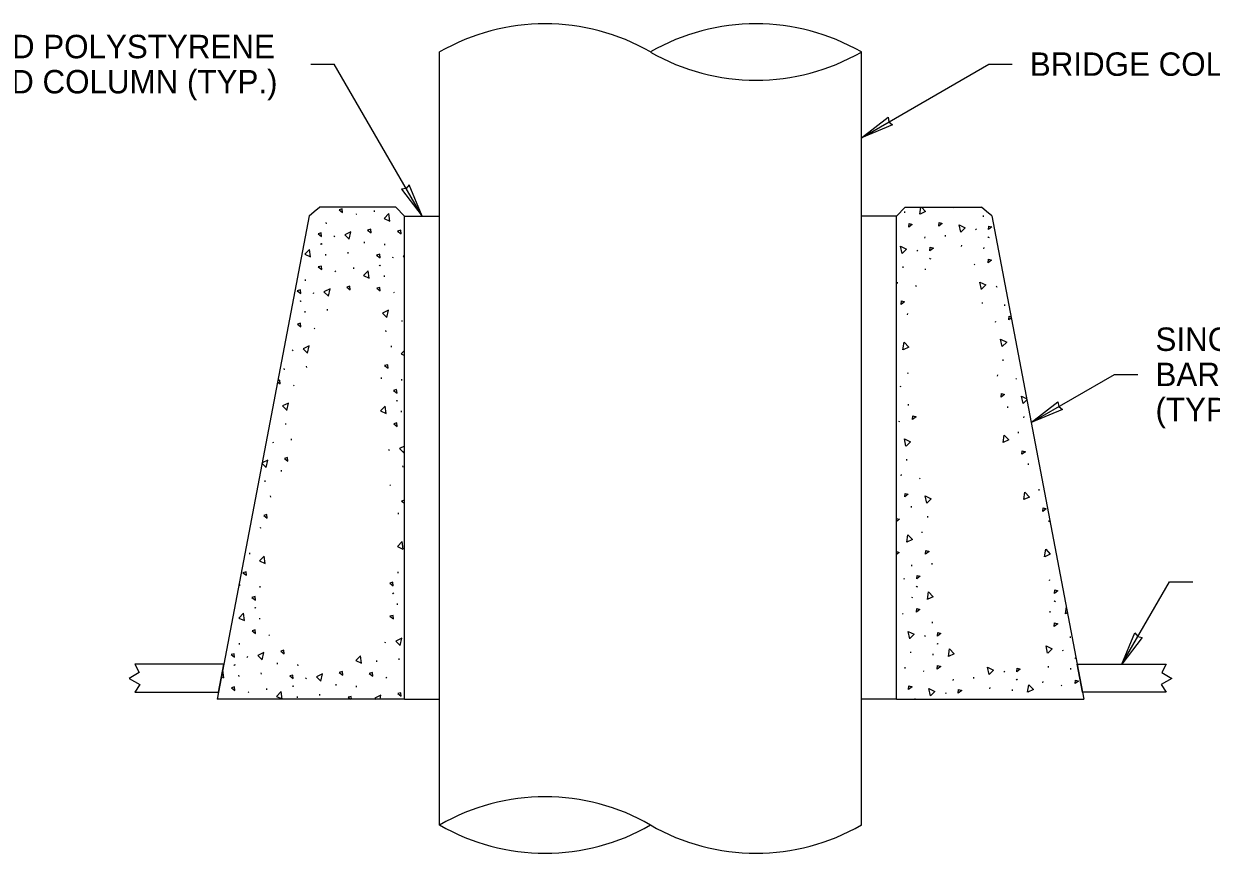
# Model space of a CAD drawing. Extents: x 99862 to 103151, y 100000 to 102076.
# Drawn here: x 100993 to 101804, y 100865 to 101431 of the extents above; entities that cross this region are included whole.
import ezdxf

# ---------------------------------------------------------------- set-up
doc = ezdxf.new("R2010")
doc.units = 0
for name, color, linetype in [('Level 13', 7, 'Continuous'), ('Level 15', 7, 'Continuous'), ('Level 2', 7, 'Continuous'), ('Level 20', 7, 'Continuous'), ('Level 45', 7, 'Continuous'), ('Level 49', 7, 'Continuous')]:
    doc.layers.add(name, color=color, linetype=linetype)

msp = doc.modelspace()

# ---------------------------------------------------------------- linework, layer by layer
at = {"layer": 'Level 13'}
for p, q in [((101220.06, 101301.42), (101219.54, 101301.04)), ((101232.44, 101302.97), (101232.38, 101303.84)), ((101594.39, 101302.2), (101594.45, 101303.07)), ((101627.68, 101306.07), (101628.17, 101305.71)), ((101648.21, 101299.49), (101648.27, 101300.36)), ((101199.51, 101294.82), (101199.45, 101295.69)), ((101642.77, 101291.26), (101643.12, 101290.54)), ((101204.95, 101286.59), (101204.6, 101285.87)), ((101225.56, 101281.47), (101225.5, 101282.34)), ((101608.23, 101284.94), (101608.29, 101285.81)), ((101622.16, 101286.13), (101622.22, 101287.01)), ((101651.22, 101285.75), (101651.74, 101285.37)), ((101651.62, 101285.68), (101652.14, 101285.3)), ((101196.09, 101281.01), (101195.58, 101280.63)), ((101196.5, 101281.08), (101195.98, 101280.7)), ((101214.44, 101274.55), (101214.38, 101275.42)), ((101239.48, 101280.27), (101239.42, 101281.14)), ((101602.79, 101276.71), (101603.15, 101275.99)), ((101633.28, 101279.22), (101633.34, 101280.09)), ((101648.55, 101277.77), (101648.61, 101278.64)), ((101199.17, 101273.1), (101199.11, 101273.98)), ((101236.07, 101266.46), (101235.55, 101266.08)), ((101236.47, 101266.53), (101235.95, 101266.15)), ((101244.93, 101272.04), (101244.57, 101271.32)), ((101611.25, 101271.2), (101611.77, 101270.82)), ((101611.65, 101271.13), (101612.17, 101270.75)), ((101641.85, 101267.11), (101642.36, 101266.73)), ((101205.87, 101262.44), (101205.36, 101262.06)), ((101218.25, 101263.99), (101218.19, 101264.86)), ((101239.14, 101258.55), (101239.08, 101259.43)), ((101593.31, 101264.67), (101593.37, 101265.54)), ((101608.58, 101263.22), (101608.64, 101264.09)), ((101185.32, 101255.84), (101185.26, 101256.71)), ((101589.5, 101254.1), (101589.56, 101254.98)), ((101601.87, 101252.56), (101602.39, 101252.18)), ((101656.95, 101252.28), (101657.31, 101251.56)), ((101181.91, 101242.03), (101181.39, 101241.65)), ((101182.31, 101242.1), (101181.79, 101241.72)), ((101190.77, 101247.61), (101190.41, 101246.89)), ((101245.85, 101247.89), (101245.33, 101247.51)), ((101184.98, 101234.12), (101184.92, 101235)), ((101200.25, 101235.57), (101200.19, 101236.44)), ((101647.47, 101240.24), (101647.53, 101241.11)), ((101662.74, 101238.79), (101662.8, 101239.66)), ((101251.34, 101227.94), (101251.28, 101228.81)), ((101596.38, 101232.6), (101596.44, 101233.48)), ((101656.03, 101228.13), (101656.55, 101227.75)), ((101191.69, 101223.46), (101191.17, 101223.08)), ((101240.22, 101221.02), (101240.16, 101221.89)), ((101244.03, 101210.46), (101243.97, 101211.33)), ((101176.58, 101208.63), (101176.22, 101207.91)), ((101661.65, 101201.26), (101661.72, 101202.13)), ((101170.79, 101195.14), (101170.73, 101196.02)), ((101186.06, 101196.59), (101186, 101197.46)), ((101596.64, 101192.43), (101596.7, 101193.3)), ((101237.15, 101188.96), (101237.09, 101189.83)), ((101251.08, 101187.76), (101251.02, 101188.64)), ((101657.85, 101190.69), (101657.91, 101191.56)), ((101670.22, 101189.15), (101670.74, 101188.77)), ((101177.5, 101184.48), (101176.98, 101184.1)), ((101591.2, 101184.2), (101591.55, 101183.48)), ((101247.66, 101173.96), (101247.15, 101173.58)), ((101248.07, 101174.02), (101247.55, 101173.64)), ((101596.98, 101170.71), (101597.04, 101171.58)), ((101664.73, 101169.19), (101664.79, 101170.07)), ((101250.74, 101166.05), (101250.68, 101166.92)), ((101675.84, 101162.28), (101675.9, 101163.15)), ((101171.88, 101157.61), (101171.82, 101158.48)), ((101590.28, 101160.05), (101590.79, 101159.67)), ((101672.03, 101151.71), (101672.09, 101152.59)), ((101163.31, 101145.5), (101162.79, 101145.12)), ((101175.69, 101147.05), (101175.63, 101147.92)), ((101242.33, 101140.55), (101241.98, 101139.83)), ((101251.82, 101128.51), (101251.76, 101129.39)), ((101595.9, 101133.18), (101595.96, 101134.05)), ((101678.91, 101130.21), (101678.97, 101131.09)), ((101168.81, 101125.55), (101168.74, 101126.42)), ((101592.09, 101122.62), (101592.15, 101123.49)), ((101604.46, 101121.07), (101604.98, 101120.69)), ((101157.69, 101118.63), (101157.63, 101119.5)), ((101243.26, 101116.4), (101242.74, 101116.03)), ((101686.22, 101112.73), (101686.28, 101113.61)), ((101161.5, 101108.07), (101161.44, 101108.94)), ((101248.75, 101096.45), (101248.69, 101097.32)), ((101598.97, 101101.12), (101599.03, 101101.99)), ((101610.09, 101094.2), (101610.15, 101095.07)), ((101693.1, 101091.23), (101693.16, 101092.11)), ((101154.62, 101086.57), (101154.56, 101087.44)), ((101588.81, 101085.86), (101588.97, 101085.73)), ((101606.28, 101083.64), (101606.34, 101084.51)), ((101147.31, 101069.09), (101147.25, 101069.96)), ((101248.49, 101056.27), (101248.43, 101057.15)), ((101599.23, 101060.94), (101599.29, 101061.81)), ((101613.16, 101062.14), (101613.22, 101063.01)), ((101140.43, 101047.59), (101140.37, 101048.46)), ((101154.36, 101046.39), (101154.3, 101047.26)), ((101593.79, 101052.71), (101594.14, 101051.99)), ((101602.24, 101047.2), (101602.76, 101046.82)), ((101602.65, 101047.13), (101603.16, 101046.75)), ((101693.36, 101051.06), (101693.42, 101051.93)), ((101245.07, 101042.47), (101244.56, 101042.09)), ((101245.48, 101042.54), (101244.96, 101042.16)), ((101599.57, 101039.22), (101599.63, 101040.1)), ((101150.94, 101032.58), (101150.43, 101032.21)), ((101151.34, 101032.65), (101150.83, 101032.27)), ((101248.15, 101034.56), (101248.09, 101035.43)), ((101696.37, 101037.32), (101696.89, 101036.94)), ((101696.78, 101037.25), (101697.29, 101036.87)), ((101154.02, 101024.68), (101153.96, 101025.55)), ((101592.87, 101028.56), (101593.38, 101028.18)), ((101613.41, 101021.96), (101613.48, 101022.83)), ((101693.7, 101029.34), (101693.76, 101030.21)), ((101140.17, 101007.41), (101140.11, 101008.29)), ((101160.72, 101014.01), (101160.2, 101013.63)), ((101239.74, 101009.07), (101239.39, 101008.35)), ((101607.97, 101013.73), (101608.33, 101013.01)), ((101616.43, 101008.22), (101616.95, 101007.84)), ((101616.83, 101008.15), (101617.35, 101007.77)), ((101707.55, 101012.08), (101707.61, 101012.95)), ((101145.61, 100999.18), (101145.26, 100998.46)), ((101598.49, 101001.69), (101598.55, 101002.56)), ((101613.76, 101000.24), (101613.82, 101001.12)), ((101702.11, 101003.85), (101702.46, 101003.13)), ((101136.75, 100993.6), (101136.24, 100993.23)), ((101137.16, 100993.67), (101136.64, 100993.29)), ((101166.22, 100994.06), (101166.15, 100994.93)), ((101180.14, 100992.86), (101180.08, 100993.74)), ((101233.96, 100995.58), (101233.9, 100996.45)), ((101249.23, 100997.03), (101249.17, 100997.9)), ((101594.68, 100991.13), (101594.74, 100992)), ((101692.62, 100991.81), (101692.68, 100992.68)), ((101707.89, 100990.36), (101707.95, 100991.23)), ((101710.56, 100998.34), (101711.08, 100997.96)), ((101710.96, 100998.27), (101711.48, 100997.89)), ((101139.83, 100985.7), (101139.77, 100986.57)), ((101155.1, 100987.14), (101155.04, 100988.02)), ((101185.58, 100984.64), (101185.23, 100983.91)), ((101240.66, 100984.92), (101240.15, 100984.54)), ((101607.05, 100989.58), (101607.57, 100989.2)), ((101627.6, 100982.98), (101627.66, 100983.85)), ((101641.53, 100984.18), (101641.59, 100985.05)), ((101662.13, 100989.3), (101662.49, 100988.58)), ((101670.59, 100983.79), (101671.11, 100983.41)), ((101670.99, 100983.72), (101671.51, 100983.34)), ((101146.53, 100975.03), (101146.02, 100974.65)), ((101158.91, 100976.58), (101158.85, 100977.45)), ((101176.73, 100979.06), (101176.21, 100978.68)), ((101177.13, 100979.12), (101176.61, 100978.75)), ((101206.19, 100979.51), (101206.13, 100980.38)), ((101220.12, 100978.32), (101220.06, 100979.19)), ((101622.16, 100974.75), (101622.52, 100974.03)), ((101652.65, 100977.26), (101652.71, 100978.13)), ((101667.92, 100975.81), (101667.98, 100976.69)), ((101688.81, 100981.24), (101688.87, 100982.12)), ((101701.19, 100979.7), (101701.7, 100979.32)), ((101179.8, 100971.15), (101179.74, 100972.02)), ((101195.07, 100972.59), (101195.01, 100973.47)), ((101225.56, 100970.09), (101225.55, 100970.07)), ((101601.59, 100970.07), (101601.62, 100970.5))]:
    msp.add_line(p, q, dxfattribs=at)
for points in [[(101210.51, 101302.44), (101210.27, 101304.89), (101208.14, 101304.25), (101210.51, 101302.44)], [(101242.88, 101296.61), (101242.18, 101301.69), (101239, 101298.4), (101242.8, 101296.64)], [(101604.84, 101301.28), (101605.5, 101306.07)], [(101605.82, 101306.07), (101608.72, 101303.07), (101604.92, 101301.31)], [(101230.02, 101288.59), (101229.78, 101291.04), (101227.65, 101290.39), (101230.02, 101288.59)], [(101597.24, 101292.56), (101597.48, 101295.01), (101599.6, 101294.36), (101597.24, 101292.56)], [(101617.7, 101293.25), (101617.94, 101295.7), (101620.07, 101295.06), (101617.7, 101293.25)], [(101632.63, 101288.96), (101631.55, 101293.97), (101635.67, 101291.98), (101632.7, 101289.02)], [(101651.56, 101290.79), (101651.8, 101293.24), (101653.93, 101292.59), (101651.56, 101290.79)], [(101196.16, 101286.12), (101195.91, 101288.57), (101193.79, 101287.93), (101196.16, 101286.12)], [(101215.09, 101284.3), (101216.16, 101289.31), (101212.05, 101287.31), (101215.02, 101284.36)], [(101250.48, 101287.89), (101250.24, 101290.34), (101248.12, 101289.7), (101250.48, 101287.89)], [(101188.72, 101272.18), (101188.02, 101277.26), (101184.84, 101273.97), (101188.64, 101272.21)], [(101592.66, 101274.42), (101591.58, 101279.43), (101595.69, 101277.43), (101592.73, 101274.47)], [(101611.59, 101276.24), (101611.83, 101278.69), (101613.96, 101278.04), (101611.59, 101276.24)], [(101236.13, 101271.57), (101235.89, 101274.02), (101233.76, 101273.38), (101236.13, 101271.57)], [(101252.81, 101273.14), (101252.02, 101272.76), (101252.81, 101271.98)], [(101651.4, 101268.13), (101651.64, 101270.58), (101653.76, 101269.93), (101651.4, 101268.13)], [(101196.32, 101263.46), (101196.08, 101265.91), (101193.96, 101265.27), (101196.32, 101263.46)], [(101228.69, 101257.63), (101227.99, 101262.71), (101224.81, 101259.42), (101228.61, 101257.66)], [(101200.9, 101245.32), (101201.98, 101250.33), (101197.86, 101248.33), (101200.83, 101245.38)], [(101215.83, 101249.61), (101215.59, 101252.06), (101213.46, 101251.41), (101215.83, 101249.61)], [(101236.29, 101248.91), (101236.05, 101251.36), (101233.93, 101250.72), (101236.29, 101248.91)], [(101646.82, 101249.98), (101645.74, 101254.99), (101649.85, 101253), (101646.88, 101250.04)], [(101181.97, 101247.14), (101181.73, 101249.59), (101179.6, 101248.95), (101181.97, 101247.14)], [(101591.92, 101239.72), (101592.16, 101242.17), (101594.28, 101241.53), (101591.92, 101239.72)], [(101240.87, 101230.77), (101241.95, 101235.78), (101237.84, 101233.78), (101240.81, 101230.83)], [(101182.13, 101224.48), (101181.89, 101226.93), (101179.77, 101226.29), (101182.13, 101224.48)], [(101665.58, 101229.15), (101665.83, 101231.6), (101667.06, 101231.22)], [(101667.22, 101230.4), (101665.58, 101229.15)], [(101186.71, 101206.34), (101187.79, 101211.35), (101183.68, 101209.35), (101186.65, 101206.4)], [(101593.24, 101208.77), (101593.94, 101213.85), (101597.12, 101210.56), (101593.32, 101208.8)], [(101661, 101211), (101659.93, 101216.01), (101664.04, 101214.02), (101661.07, 101211.06)], [(101252.81, 101208.18), (101250.59, 101205.9), (101252.81, 101204.87)], [(101241.62, 101196.08), (101241.37, 101198.53), (101239.25, 101197.88), (101241.62, 101196.08)], [(101166.11, 101186.9), (101167.95, 101185.5)], [(101167.95, 101185.5), (101167.7, 101187.95), (101166.23, 101187.5)], [(101247.73, 101179.06), (101247.48, 101181.51), (101245.36, 101180.87), (101247.73, 101179.06)], [(101660.26, 101176.31), (101660.51, 101178.76), (101662.63, 101178.12), (101660.26, 101176.31)], [(101675.19, 101172.02), (101674.12, 101177.04), (101677.72, 101175.29)], [(101172.53, 101167.36), (101173.6, 101172.37), (101169.49, 101170.37), (101172.46, 101167.42)], [(101240.29, 101165.12), (101239.59, 101170.2), (101236.41, 101166.92), (101240.21, 101165.15)], [(101677.84, 101174.65), (101675.26, 101172.08)], [(101599.83, 101161.07), (101600.07, 101163.52), (101602.19, 101162.88), (101599.83, 101161.07)], [(101247.89, 101156.4), (101247.65, 101158.85), (101245.52, 101158.21), (101247.89, 101156.4)], [(101595.25, 101142.93), (101594.17, 101147.94), (101598.28, 101145.94), (101595.32, 101142.98)], [(101661.59, 101145.36), (101662.29, 101150.44), (101665.47, 101147.15), (101661.67, 101145.39)], [(101252.81, 101142.91), (101249.43, 101141.27), (101252.4, 101138.32)], [(101252.47, 101138.26), (101252.81, 101139.83)], [(101674.45, 101137.33), (101674.69, 101139.78), (101676.82, 101139.14), (101674.45, 101137.33)], [(101155.5, 101131.19), (101158.27, 101128.44)], [(101158.34, 101128.38), (101159.41, 101133.39), (101155.56, 101131.52)], [(101173.27, 101132.67), (101173.03, 101135.12), (101170.9, 101134.47), (101173.27, 101132.67)], [(101252.81, 101105.97), (101250.85, 101105.37), (101252.81, 101103.88)], [(101594.51, 101108.23), (101594.75, 101110.69), (101596.87, 101110.04), (101594.51, 101108.23)], [(101609.43, 101103.95), (101608.36, 101108.96), (101612.47, 101106.96), (101609.5, 101104)], [(101675.78, 101106.38), (101676.48, 101111.46), (101679.66, 101108.17), (101675.86, 101106.41)], [(101159.08, 101093.69), (101158.84, 101096.14), (101156.71, 101095.49), (101159.08, 101093.69)], [(101688.64, 101098.35), (101688.88, 101100.8), (101691, 101100.16), (101688.64, 101098.35)], [(101588.81, 101093.62), (101590.76, 101093.03), (101588.81, 101091.53)], [(101595.83, 101077.28), (101596.54, 101082.36), (101599.72, 101079.07), (101595.91, 101077.31)], [(101251.89, 101072.62), (101251.18, 101077.69), (101248, 101074.41), (101251.8, 101072.65)], [(101608.69, 101069.25), (101608.94, 101071.71), (101611.06, 101071.06), (101608.69, 101069.25)], [(101689.96, 101067.4), (101690.67, 101072.48), (101693.85, 101069.19), (101690.05, 101067.43)], [(101157.76, 101062.73), (101157.05, 101067.81), (101153.87, 101064.53), (101157.67, 101062.76)], [(101588.81, 101070.91), (101590.6, 101070.37), (101588.81, 101069)], [(101144.89, 101054.71), (101144.65, 101057.16), (101142.53, 101056.51), (101144.89, 101054.71)], [(101245.14, 101047.57), (101244.89, 101050.02), (101242.77, 101049.38), (101245.14, 101047.57)], [(101602.58, 101052.24), (101602.83, 101054.69), (101604.95, 101054.05), (101602.58, 101052.24)], [(101151, 101037.69), (101150.76, 101040.14), (101148.64, 101039.5), (101151, 101037.69)], [(101610.02, 101038.3), (101610.72, 101043.38), (101613.9, 101040.09), (101610.1, 101038.33)], [(101696.72, 101042.36), (101696.96, 101044.81), (101699.08, 101044.16), (101696.72, 101042.36)], [(101602.42, 101029.58), (101602.66, 101032.03), (101604.78, 101031.39), (101602.42, 101029.58)], [(101704.15, 101028.42), (101704.8, 101033.1)], [(101143.57, 101023.75), (101142.86, 101028.83), (101139.68, 101025.55), (101143.48, 101023.78)], [(101245.3, 101024.92), (101245.06, 101027.37), (101242.93, 101026.72), (101245.3, 101024.92)], [(101705.57, 101029.07), (101704.23, 101028.45)], [(101151.17, 101015.03), (101150.93, 101017.48), (101148.8, 101016.84), (101151.17, 101015.03)], [(101597.84, 101011.44), (101596.76, 101016.45), (101600.87, 101014.45), (101597.91, 101011.5)], [(101616.77, 101013.26), (101617.01, 101015.71), (101619.14, 101015.07), (101616.77, 101013.26)], [(101696.55, 101019.7), (101696.79, 101022.15), (101698.92, 101021.51), (101696.55, 101019.7)], [(101249.88, 101006.77), (101250.96, 101011.78), (101246.84, 101009.78), (101249.81, 101006.83)], [(101691.97, 101001.56), (101690.9, 101006.57), (101695.01, 101004.57), (101692.04, 101001.61)], [(101136.82, 100998.71), (101136.57, 101001.16), (101134.45, 101000.52), (101136.82, 100998.71)], [(101155.75, 100996.89), (101156.82, 101001.9), (101152.71, 100999.9), (101155.68, 100996.95)], [(101170.68, 101001.18), (101170.44, 101003.63), (101168.31, 101002.98), (101170.68, 101001.18)], [(101223.51, 100994.66), (101222.81, 100999.73), (101219.63, 100996.45), (101223.43, 100994.69)], [(101624.21, 100999.32), (101624.91, 101004.4), (101628.09, 101001.11), (101624.29, 100999.35)], [(101616.61, 100990.6), (101616.85, 100993.05), (101618.97, 100992.41), (101616.61, 100990.6)], [(101652, 100987.01), (101650.92, 100992.02), (101655.03, 100990.02), (101652.07, 100987.06)], [(101670.93, 100988.83), (101671.17, 100991.28), (101673.3, 100990.64), (101670.93, 100988.83)], [(101127.75, 100985.52), (101129.3, 100984.8)], [(101129.38, 100984.77), (101128.68, 100989.85), (101128.55, 100989.72)], [(101176.79, 100984.16), (101176.55, 100986.61), (101174.42, 100985.97), (101176.79, 100984.16)], [(101195.72, 100982.34), (101196.8, 100987.35), (101192.68, 100985.35), (101195.65, 100982.4)], [(101210.65, 100986.63), (101210.41, 100989.08), (101208.28, 100988.44), (101210.65, 100986.63)], [(101231.11, 100985.94), (101230.87, 100988.39), (101228.75, 100987.74), (101231.11, 100985.94)], [(101710.74, 100980.72), (101710.98, 100983.17), (101713.1, 100982.53), (101710.74, 100980.72)], [(101136.98, 100976.05), (101136.74, 100978.5), (101134.61, 100977.86), (101136.98, 100976.05)], [(101169.35, 100970.23), (101168.65, 100975.3), (101165.47, 100972.02), (101169.27, 100970.26)], [(101250.62, 100972.08), (101250.38, 100974.53), (101248.26, 100973.89), (101250.62, 100972.08)], [(101597.1, 100976.75), (101597.34, 100979.2), (101599.46, 100978.55), (101597.1, 100976.75)], [(101612.03, 100972.46), (101610.95, 100977.47), (101615.06, 100975.47), (101612.09, 100972.52)], [(101630.96, 100974.28), (101631.2, 100976.73), (101633.32, 100976.09), (101630.96, 100974.28)], [(101678.37, 100974.89), (101679.07, 100979.97), (101682.25, 100976.68), (101678.45, 100974.92)], [(101216.72, 100970.07), (101216.52, 100972.06), (101214.39, 100971.42), (101216.16, 100970.07)], [(101236.18, 100970.07), (101236.77, 100972.8), (101232.66, 100970.81), (101233.39, 100970.07)]]:
    msp.add_lwpolyline(points, dxfattribs=at)
at = {"layer": 'Level 15'}
for p, q in [((101188.92, 101403.79), (101204.92, 101403.79)), ((101264.81, 101300.07), (101204.92, 101403.79)), ((101564.81, 101353.55), (101651.83, 101403.79)), ((101651.83, 101403.79), (101667.83, 101403.79)), ((101680.8, 101159.12), (101737.66, 101191.95)), ((101737.66, 101191.95), (101753.66, 101191.95)), ((101742.62, 100994.07), (101775.12, 101050.36)), ((101775.12, 101050.36), (101791.12, 101050.36))]:
    msp.add_line(p, q, dxfattribs=at)
for points in [[(101564.81, 101353.55), (101583.09, 101367.55), (101583.66, 101364.43), (101586.07, 101362.38)], [(101264.81, 101300.07), (101255.98, 101321.33), (101253.92, 101318.93), (101250.81, 101318.35)], [(101680.8, 101159.12), (101699.07, 101173.12), (101699.65, 101170), (101702.06, 101167.95)], [(101742.62, 100994.07), (101751.45, 101015.33), (101753.51, 101012.93), (101756.62, 101012.35)]]:
    msp.add_lwpolyline(points, close=True, dxfattribs=at)
at = {"layer": 'Level 2'}
for p, q in [((101276.81, 100884.2), (101276.81, 101412.08)), ((101564.81, 100884.2), (101564.81, 101412.08)), ((101187.69, 101300.17), (101124.81, 100970.07)), ((101187.69, 101300.17), (101191.25, 101303.13)), ((101191.25, 101303.13), (101194.81, 101306.07)), ((101246.81, 101306.07), (101194.81, 101306.07)), ((101246.81, 101306.07), (101252.81, 101300.07)), ((101252.81, 100970.07), (101252.81, 101300.07)), ((101594.81, 101306.07), (101588.81, 101300.07)), ((101588.81, 100970.07), (101588.81, 101300.07)), ((101594.81, 101306.07), (101646.81, 101306.07)), ((101650.37, 101303.13), (101646.81, 101306.07)), ((101653.93, 101300.17), (101650.37, 101303.13)), ((101653.93, 101300.17), (101716.81, 100970.07)), ((101252.81, 100970.07), (101124.81, 100970.07)), ((101588.81, 100970.07), (101716.81, 100970.07))]:
    msp.add_line(p, q, dxfattribs=at)
for centre, start, end in [((101348.81, 101287.37), 60, 120), ((101492.81, 101287.37), 60, 120), ((101492.81, 101536.78), 240, 300), ((101348.81, 100759.49), 60, 120), ((101348.81, 101008.91), 240, 300), ((101492.81, 101008.91), 240, 300)]:
    msp.add_arc(centre, 144, start, end, dxfattribs=at)
at = {"layer": 'Level 45'}
for p, q in [((101252.81, 101300.07), (101276.81, 101300.07)), ((101588.81, 101300.07), (101564.81, 101300.07)), ((101252.81, 100970.07), (101276.81, 100970.07)), ((101588.81, 100970.07), (101564.81, 100970.07))]:
    msp.add_line(p, q, dxfattribs=at)
at = {"layer": 'Level 49'}
for p, q in [((101129.38, 100994.07), (101068.61, 100994.07)), ((101068.61, 100994.07), (101071.6, 100988.4)), ((101125.72, 100974.87), (101129.38, 100994.07)), ((101712.24, 100994.07), (101773.01, 100994.07)), ((101715.9, 100974.87), (101712.24, 100994.07)), ((101773.01, 100994.07), (101770.01, 100988.4)), ((101071.6, 100988.4), (101064.81, 100984.25)), ((101064.81, 100984.25), (101072, 100980.25)), ((101776.81, 100984.25), (101769.61, 100980.25)), ((101770.01, 100988.4), (101776.81, 100984.25)), ((101072, 100980.25), (101068.61, 100974.87)), ((101068.61, 100974.87), (101125.72, 100974.87)), ((101773.01, 100974.87), (101715.9, 100974.87)), ((101769.61, 100980.25), (101773.01, 100974.87))]:
    msp.add_line(p, q, dxfattribs=at)

# ---------------------------------------------------------------- texts
at = {"layer": 'Level 20'}
for s, p in [('3" EXPANDED POLYSTYRENE ', (100857.08, 101407.8)), ('BRIDGE COLUMN', (101679.84, 101395.8)), ('AROUND COLUMN (TYP.)', (100906.98, 101383.8)), ('SINGLE-SLOPE CONCRETE', (101765.66, 101207.95)), ('BARRIER: VERTICAL BACK', (101765.66, 101183.95)), ('(TYP.)', (101765.66, 101159.95))]:
    msp.add_text(s, height=16, dxfattribs=at).set_placement(p)

doc.saveas('drawing.dxf')
